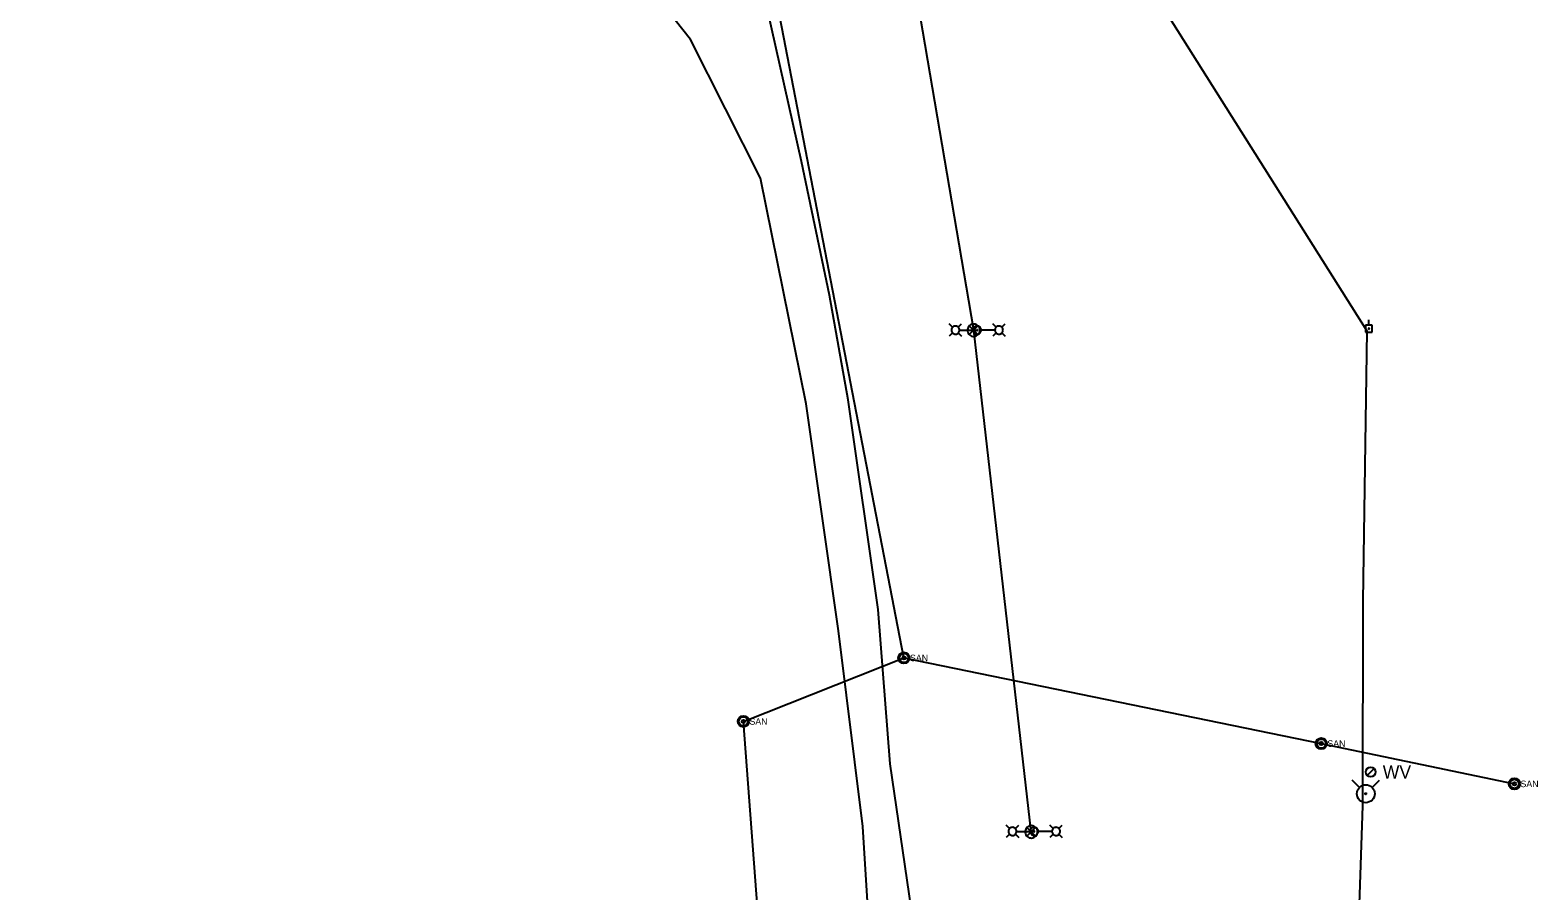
# Model space of a CAD drawing. Extents: x 600849 to 606371, y 330010 to 403088.
# Drawn here: x 603785 to 604588, y 348308 to 348767 of the extents above; entities that cross this region are included whole.
import ezdxf

# ---------------------------------------------------------------- set-up
doc = ezdxf.new("R2010")
doc.units = 0
for name, color, linetype in [('E_FTMS_Conduit', 7, 'Continuous'), ('E_LTG', 7, 'Continuous'), ('E_LTG_CID', 7, 'Continuous'), ('E_UTL_E_UG', 7, 'Continuous'), ('E_UTL_EPowerPole', 7, 'Continuous'), ('E_UTL_FO_UG_QWEST', 7, 'Continuous'), ('E_UTL_Overhead', 7, 'Continuous'), ('E_UTL_SAN', 7, 'Continuous'), ('E_UTL_SAN_UG', 7, 'Continuous'), ('E_UTL_W', 7, 'Continuous'), ('E_UTL_WHydrant', 7, 'Continuous')]:
    doc.layers.add(name, color=color, linetype=linetype)

msp = doc.modelspace()

# ---------------------------------------------------------------- linework, layer by layer
at = {"layer": 'E_FTMS_Conduit'}
msp.add_lwpolyline([(604255.37, 348290.94), (604242.89, 348375.97), (604236.47, 348458.2), (604220.45, 348569.91), (604210.62, 348625.55), (604195.75, 348696.84), (604168.29, 348818.93), (604159.32, 348850.28), (604151.36, 348880.73), (604135.81, 348939.85), (604122.74, 348988.04)], dxfattribs=at)
at = {"layer": 'E_LTG'}
for points in [[(604276.13, 348608.49), (604274.36, 348610.26)], [(604276.13, 348605.44), (604274.36, 348603.66)], [(604279.83, 348606.97), (604279.79, 348607.38), (604279.68, 348607.77), (604279.49, 348608.14), (604279.23, 348608.47), (604278.92, 348608.74), (604278.56, 348608.94), (604278.17, 348609.08), (604277.76, 348609.14), (604277.35, 348609.12), (604276.95, 348609.02), (604276.57, 348608.85), (604276.23, 348608.61), (604275.95, 348608.31), (604275.72, 348607.96), (604275.57, 348607.58), (604275.49, 348607.17), (604275.49, 348606.76), (604275.57, 348606.35), (604275.72, 348605.97), (604275.95, 348605.62), (604276.23, 348605.32), (604276.57, 348605.08), (604276.95, 348604.91), (604277.35, 348604.81), (604277.76, 348604.79), (604278.17, 348604.85), (604278.56, 348604.99), (604278.92, 348605.19), (604279.23, 348605.46), (604279.49, 348605.79), (604279.68, 348606.16), (604279.79, 348606.55), (604279.83, 348606.97)], [(604279.18, 348608.49), (604280.96, 348610.26)], [(604279.18, 348605.44), (604280.96, 348603.66)], [(604279.87, 348606.96), (604287.05, 348606.96)], [(604290.66, 348606.91), (604290.6, 348607.53), (604290.42, 348608.13), (604290.14, 348608.69), (604289.75, 348609.18), (604289.27, 348609.6), (604288.73, 348609.91), (604288.14, 348610.11), (604287.52, 348610.2), (604286.89, 348610.17), (604286.28, 348610.03), (604285.71, 348609.76), (604285.2, 348609.4), (604284.77, 348608.95), (604284.43, 348608.42), (604284.19, 348607.84), (604284.07, 348607.22), (604284.07, 348606.59), (604284.19, 348605.98), (604284.43, 348605.39), (604284.77, 348604.87), (604285.2, 348604.41), (604285.71, 348604.05), (604286.28, 348603.79), (604286.89, 348603.64), (604287.52, 348603.61), (604288.14, 348603.7), (604288.73, 348603.91), (604289.27, 348604.22), (604289.75, 348604.63), (604290.14, 348605.12), (604290.42, 348605.68), (604290.6, 348606.28), (604290.66, 348606.91)], [(604289.62, 348609.24), (604285.01, 348604.58)], [(604285.01, 348609.19), (604289.66, 348604.54)], [(604291.4, 348606.96), (604291.36, 348607.38), (604291.24, 348607.77), (604291.05, 348608.14), (604290.8, 348608.47), (604290.49, 348608.74), (604290.13, 348608.94), (604289.74, 348609.08), (604289.33, 348609.14), (604288.91, 348609.12), (604288.51, 348609.02), (604288.14, 348608.85), (604287.8, 348608.61), (604287.51, 348608.31), (604287.29, 348607.96), (604287.14, 348607.58), (604287.06, 348607.17), (604287.06, 348606.76), (604287.14, 348606.35), (604287.29, 348605.97), (604287.51, 348605.62), (604287.8, 348605.32), (604288.14, 348605.08), (604288.51, 348604.91), (604288.91, 348604.81), (604289.33, 348604.79), (604289.74, 348604.85), (604290.13, 348604.99), (604290.49, 348605.19), (604290.8, 348605.46), (604291.05, 348605.79), (604291.24, 348606.16), (604291.36, 348606.55), (604291.4, 348606.96)], [(604289.39, 348606.96), (604289.39, 348607), (604289.38, 348607.03), (604289.36, 348607.05), (604289.34, 348607.08), (604289.32, 348607.1), (604289.29, 348607.12), (604289.26, 348607.13), (604289.23, 348607.13), (604289.2, 348607.13), (604289.17, 348607.12), (604289.14, 348607.11), (604289.11, 348607.09), (604289.09, 348607.07), (604289.08, 348607.04), (604289.06, 348607.01), (604289.06, 348606.98), (604289.06, 348606.95), (604289.06, 348606.92), (604289.08, 348606.89), (604289.09, 348606.86), (604289.11, 348606.84), (604289.14, 348606.82), (604289.17, 348606.81), (604289.2, 348606.8), (604289.23, 348606.8), (604289.26, 348606.8), (604289.29, 348606.81), (604289.32, 348606.83), (604289.34, 348606.85), (604289.36, 348606.87), (604289.38, 348606.9), (604289.39, 348606.93), (604289.39, 348606.96)], [(604298.61, 348606.97), (604291.44, 348606.97)], [(604299.3, 348608.49), (604297.53, 348610.26)], [(604299.3, 348605.44), (604297.53, 348603.67)], [(604303, 348606.96), (604302.96, 348607.38), (604302.85, 348607.77), (604302.66, 348608.14), (604302.4, 348608.47), (604302.09, 348608.74), (604301.73, 348608.94), (604301.34, 348609.08), (604300.93, 348609.14), (604300.52, 348609.12), (604300.11, 348609.02), (604299.74, 348608.85), (604299.4, 348608.61), (604299.12, 348608.31), (604298.89, 348607.96), (604298.74, 348607.58), (604298.66, 348607.17), (604298.66, 348606.76), (604298.74, 348606.35), (604298.89, 348605.97), (604299.12, 348605.62), (604299.4, 348605.32), (604299.74, 348605.08), (604300.11, 348604.91), (604300.52, 348604.81), (604300.93, 348604.79), (604301.34, 348604.85), (604301.73, 348604.99), (604302.09, 348605.19), (604302.4, 348605.46), (604302.66, 348605.79), (604302.85, 348606.16), (604302.96, 348606.55), (604303, 348606.96)], [(604302.35, 348608.49), (604304.13, 348610.26)], [(604302.35, 348605.44), (604304.13, 348603.67)], [(604306.51, 348341.46), (604304.73, 348343.23)], [(604310.21, 348339.93), (604310.17, 348340.35), (604310.06, 348340.74), (604309.87, 348341.11), (604309.61, 348341.44), (604309.3, 348341.71), (604308.94, 348341.91), (604308.55, 348342.05), (604308.14, 348342.11), (604307.73, 348342.09), (604307.32, 348341.99), (604306.95, 348341.82), (604306.61, 348341.58), (604306.33, 348341.28), (604306.1, 348340.93), (604305.95, 348340.55), (604305.87, 348340.14), (604305.87, 348339.73), (604305.95, 348339.32), (604306.1, 348338.94), (604306.33, 348338.59), (604306.61, 348338.29), (604306.95, 348338.05), (604307.32, 348337.88), (604307.73, 348337.78), (604308.14, 348337.76), (604308.55, 348337.82), (604308.94, 348337.96), (604309.3, 348338.16), (604309.61, 348338.43), (604309.87, 348338.76), (604310.06, 348339.13), (604310.17, 348339.52), (604310.21, 348339.93)], [(604309.56, 348341.46), (604311.34, 348343.23)], [(604310.25, 348339.93), (604317.43, 348339.93)], [(604321.35, 348339.7), (604321.29, 348340.33), (604321.11, 348340.93), (604320.82, 348341.49), (604320.44, 348341.98), (604319.96, 348342.39), (604319.42, 348342.7), (604318.83, 348342.91), (604318.21, 348343), (604317.58, 348342.97), (604316.97, 348342.82), (604316.4, 348342.56), (604315.89, 348342.2), (604315.45, 348341.74), (604315.12, 348341.21), (604314.88, 348340.63), (604314.76, 348340.02), (604314.76, 348339.39), (604314.88, 348338.77), (604315.12, 348338.19), (604315.45, 348337.66), (604315.89, 348337.21), (604316.4, 348336.84), (604316.97, 348336.58), (604317.58, 348336.44), (604318.21, 348336.41), (604318.83, 348336.49), (604319.42, 348336.7), (604319.96, 348337.01), (604320.44, 348337.42), (604320.82, 348337.92), (604321.11, 348338.48), (604321.29, 348339.08), (604321.35, 348339.7)], [(604320.31, 348342.04), (604315.7, 348337.38)], [(604315.7, 348341.99), (604320.35, 348337.34)], [(604321.78, 348339.93), (604321.74, 348340.35), (604321.62, 348340.74), (604321.43, 348341.11), (604321.18, 348341.44), (604320.86, 348341.71), (604320.51, 348341.91), (604320.11, 348342.05), (604319.7, 348342.11), (604319.29, 348342.09), (604318.89, 348341.99), (604318.51, 348341.82), (604318.18, 348341.58), (604317.89, 348341.28), (604317.67, 348340.93), (604317.51, 348340.55), (604317.44, 348340.14), (604317.44, 348339.73), (604317.51, 348339.32), (604317.67, 348338.94), (604317.89, 348338.59), (604318.18, 348338.29), (604318.51, 348338.05), (604318.89, 348337.88), (604319.29, 348337.78), (604319.7, 348337.76), (604320.11, 348337.82), (604320.51, 348337.96), (604320.86, 348338.16), (604321.18, 348338.43), (604321.43, 348338.76), (604321.62, 348339.13), (604321.74, 348339.52), (604321.78, 348339.93)], [(604319.77, 348339.93), (604319.76, 348339.97), (604319.76, 348340), (604319.74, 348340.02), (604319.72, 348340.05), (604319.7, 348340.07), (604319.67, 348340.09), (604319.64, 348340.1), (604319.61, 348340.1), (604319.58, 348340.1), (604319.55, 348340.09), (604319.52, 348340.08), (604319.49, 348340.06), (604319.47, 348340.04), (604319.45, 348340.01), (604319.44, 348339.98), (604319.44, 348339.95), (604319.44, 348339.92), (604319.44, 348339.89), (604319.45, 348339.86), (604319.47, 348339.83), (604319.49, 348339.81), (604319.52, 348339.79), (604319.55, 348339.78), (604319.58, 348339.77), (604319.61, 348339.77), (604319.64, 348339.77), (604319.67, 348339.78), (604319.7, 348339.8), (604319.72, 348339.82), (604319.74, 348339.84), (604319.76, 348339.87), (604319.76, 348339.9), (604319.77, 348339.93)], [(604328.99, 348339.93), (604321.81, 348339.93)], [(604329.68, 348341.46), (604327.9, 348343.23)], [(604333.38, 348339.93), (604333.34, 348340.35), (604333.22, 348340.74), (604333.03, 348341.11), (604332.78, 348341.44), (604332.47, 348341.71), (604332.11, 348341.91), (604331.72, 348342.05), (604331.31, 348342.11), (604330.89, 348342.09), (604330.49, 348341.99), (604330.12, 348341.82), (604329.78, 348341.58), (604329.49, 348341.28), (604329.27, 348340.93), (604329.12, 348340.55), (604329.04, 348340.14), (604329.04, 348339.73), (604329.12, 348339.32), (604329.27, 348338.94), (604329.49, 348338.59), (604329.78, 348338.29), (604330.12, 348338.05), (604330.49, 348337.88), (604330.89, 348337.78), (604331.31, 348337.76), (604331.72, 348337.82), (604332.11, 348337.96), (604332.47, 348338.16), (604332.78, 348338.43), (604333.03, 348338.76), (604333.22, 348339.13), (604333.34, 348339.52), (604333.38, 348339.93)], [(604332.73, 348341.46), (604334.51, 348343.23)], [(604306.51, 348338.41), (604304.73, 348336.63)], [(604309.56, 348338.41), (604311.34, 348336.63)], [(604329.68, 348338.41), (604327.9, 348336.63)], [(604332.73, 348338.41), (604334.51, 348336.63)]]:
    msp.add_lwpolyline(points, dxfattribs=at)
at = {"layer": 'E_LTG_CID'}
for points in [[(604318.05, 348339.7), (604287.36, 348606.91), (604242.16, 348872.6), (604188.57, 349120.13), (604125.01, 349362.84), (604050.82, 349602.08), (604014.23, 349708.06), (603966.43, 349837.54), (603869.82, 350091.09), (603838.85, 350172.22), (603784.41, 350315.72), (603699.29, 350539.43), (603613.87, 350764.2), (603510.34, 351036.54), (603442.84, 351213.06), (603357.76, 351436.96)], [(604318.05, 348339.7), (604319.6, 348339.93)]]:
    msp.add_lwpolyline(points, dxfattribs=at)
at = {"layer": 'E_UTL_E_UG'}
msp.add_lwpolyline([(604287.36, 348606.91), (604289.22, 348606.96)], dxfattribs=at)
at = {"layer": 'E_UTL_EPowerPole'}
for points in [[(604499.61, 348609.59), (604495.92, 348609.59)], [(604495.92, 348609.59), (604495.92, 348605.9)], [(604495.92, 348605.9), (604499.61, 348605.9)], [(604498.04, 348607.75), (604498.03, 348607.79), (604498.02, 348607.84), (604498, 348607.88), (604497.97, 348607.91), (604497.94, 348607.94), (604497.9, 348607.97), (604497.86, 348607.98), (604497.81, 348607.99), (604497.77, 348607.99), (604497.72, 348607.98), (604497.68, 348607.96), (604497.64, 348607.93), (604497.61, 348607.9), (604497.59, 348607.86), (604497.57, 348607.82), (604497.56, 348607.77), (604497.56, 348607.73), (604497.57, 348607.68), (604497.59, 348607.64), (604497.61, 348607.6), (604497.64, 348607.57), (604497.68, 348607.54), (604497.72, 348607.52), (604497.77, 348607.51), (604497.81, 348607.51), (604497.86, 348607.52), (604497.9, 348607.53), (604497.94, 348607.56), (604497.97, 348607.59), (604498, 348607.62), (604498.02, 348607.66), (604498.03, 348607.7), (604498.04, 348607.75)], [(604497.77, 348609.59), (604497.77, 348612.5)], [(604499.61, 348605.9), (604499.61, 348609.59)]]:
    msp.add_lwpolyline(points, dxfattribs=at)
at = {"layer": 'E_UTL_FO_UG_QWEST'}
msp.add_lwpolyline([(604236.13, 348217.46), (604228.32, 348342.51), (604215.3, 348446.76), (604198.19, 348567.61), (604173.84, 348687.96), (604136.54, 348761.74), (604104.56, 348802.29), (604071.95, 348829.22), (604012.05, 348874.63), (603979.66, 348925.21), (603912.18, 349036.18), (603885.01, 349078.45), (603854.63, 349127.65), (603826.25, 349172.78), (603804.23, 349209.01), (603793.47, 349232.27)], dxfattribs=at)
at = {"layer": 'E_UTL_Overhead'}
msp.add_lwpolyline([(604478.31, 347519.68), (604483.72, 347671.98), (604483.28, 347764.14), (604485.06, 347887.98), (604486.27, 348010.92), (604488.67, 348180.49), (604494.52, 348353.63), (604494.83, 348462.74), (604496.93, 348606.36), (604375.49, 348799.31), (604376.94, 348947.02), (604379.21, 349092.24), (604380.86, 349222.2), (604382.17, 349247.08), (604392.21, 349368.46), (604406.42, 349499.8), (604417.96, 349607.66), (604418.92, 349622.62), (604430.02, 349675.12), (604460.6, 349837.98)], dxfattribs=at)
at = {"layer": 'E_UTL_SAN'}
for centre, radius in [((604250.23, 348432.35), 3), ((604250.23, 348432.35), 2.4), ((604250.23, 348432.35), 0.9), ((604164.73, 348398.52), 3), ((604164.73, 348398.52), 2.4), ((604164.73, 348398.52), 0.9), ((604472.45, 348386.75), 3), ((604472.45, 348386.75), 2.4), ((604472.45, 348386.75), 0.9), ((604575.27, 348365.28), 3), ((604575.27, 348365.28), 2.4), ((604575.27, 348365.28), 0.9)]:
    msp.add_circle(centre, radius, dxfattribs=at)
at = {"layer": 'E_UTL_SAN_UG'}
for p, q in [((604250.22, 348432.34), (604181.34, 348788.4)), ((604164.73, 348398.52), (604250.22, 348432.34)), ((604188.69, 348084.12), (604164.73, 348398.52))]:
    msp.add_line(p, q, dxfattribs=at)
for points in [[(604250.22, 348432.34), (604472.45, 348386.77)], [(604472.45, 348386.77), (604575.27, 348365.28)]]:
    msp.add_lwpolyline(points, dxfattribs=at)
at = {"layer": 'E_UTL_W'}
msp.add_lwpolyline([(604496.88, 348369.77), (604500.54, 348373.43)], dxfattribs=at)
msp.add_circle((604498.71, 348371.6), 2.59, dxfattribs=at)
at = {"layer": 'E_UTL_WHydrant'}
for points in [[(604492.8, 348363.35), (604488.91, 348367.24)], [(604499.48, 348363.35), (604503.37, 348367.24)]]:
    msp.add_lwpolyline(points, dxfattribs=at)
for radius in [4.77, 0.365]:
    msp.add_circle((604496.14, 348360.01), radius, dxfattribs=at)

# ---------------------------------------------------------------- texts
at = {"layer": 'E_UTL_SAN'}
for p in [(604253.47, 348430.58), (604167.97, 348396.75), (604475.69, 348384.98), (604578.51, 348363.51)]:
    msp.add_text('SAN', height=3.499, rotation=360, dxfattribs=at).set_placement(p)
at = {"layer": 'E_UTL_W'}
msp.add_text('WV', height=7, dxfattribs=at).set_placement((604505.19, 348368.1))

doc.saveas('drawing.dxf')
